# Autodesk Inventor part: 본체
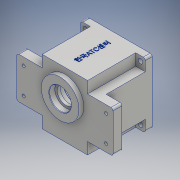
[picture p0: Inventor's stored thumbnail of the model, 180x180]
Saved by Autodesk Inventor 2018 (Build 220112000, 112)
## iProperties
Created: 2020-07
Part Number: 본체
Material: 알루미늄 6061
Document SubType Name: Modeling
Designer: admin
Density: 2.7 g/cm^3
Appearance: 알루미늄 - 평지
Mass: 876.486 g
Surface Area: 793.573 cm^2
Volume: 324.624 cm^3
Author: admin
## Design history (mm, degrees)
sketch "스케치1"
  geometry: L1 (98, 0)-(-98, 0) reference; L2 (0, -65.8)-(0, 65.8) reference; L3 (70, 0)-(70, 30); L4 (70, 30)-(33, 30); L5 (33, 30)-(33, 47); L6 (33, 47)-(-33, 47); L7 (-33, 47)-(-33, 30); L8 (-33, 30)-(-70, 30); L9 (-70, 30)-(-70, 0); L10 (70, 0)-(70, -30); L11 (70, -30)-(33, -30); L12 (33, -30)-(33, -47); L13 (33, -47)-(-33, -47); L14 (-33, -47)-(-33, -30); L15 (-33, -30)-(-70, -30); L16 (-70, -30)-(-70, 0); 1 further point
  constraints: 28 end point, 8 symmetric about line, 5 perpendicular, 2 point on line, 2 vertical
  dimensions: "d0" = 30 distance of L3.start L3.end; "d1" = 47 distance between parallel lines of L1 L6; "d2" = 140 distance between parallel lines of L9 L3; "d3" = 66 distance of L5.end L6.end
extrude "돌출1" new body sketch "스케치1" distance "d4" = 13; taper "d5" = 0 deg
sketch "스케치2"
  geometry: L1 (-98, 0)-(98, 0) reference; L2 (0, -65.8)-(0, 65.8) reference; C1 r 27.5 at (0, 11); 1 further point
  constraints: 1 centre point, 1 point on line
  dimensions: "d6" = 55 diameter of C1; "d7" = 11 distance from line of L1 C1.centre
extrude "돌출2" join sketch "스케치2" distance "d8" = 7; taper "d9" = 0 deg
sketch "스케치3"
  geometry: L1 (-98, 0)-(98, 0) reference; L2 (0, 65.8)-(0, -65.8) reference; L3 (47, -47)-(-47, -47); L4 (-47, -47)-(-47, 47); L5 (-47, 47)-(47, 47); L6 (47, 47)-(47, -47); L7 (47, -47)-(-47, 47); L8 (-47, -47)-(47, 47); 1 further point
  constraints: 12 end point, 2 midpoint, 2 parallel, 1 horizontal, 1 perpendicular
  dimensions: "d10" = 94 distance of L4.end L5.end; "d11" = 94 distance of L3.end L4.end
extrude "돌출3" join sketch "스케치3" distance "d12" = 67; taper "d13" = 0 deg
sketch "스케치5"
  geometry: L1 (33, 30)-(47, 30) reference; L2 (47, 30)-(47, 47) reference; L3 (47, 47)-(33, 47) reference; L4 (33, 47)-(33, 30) reference; L5 (-98, 0)-(98, 0) reference; L6 (0, -65.8)-(0, 65.8) reference; L7 (33, 30)-(47, 30) reference; L8 (33, 47)-(33, 30); L9 (33, 30)-(47, 30); L10 (47, 30)-(47, 47); L11 (47, 30)-(70, 30) reference; L12 (33, 47)-(33, 30) reference; L13 (47, 47)-(33, 47); L14 (-33, 47)-(-33, 30); L15 (-47, 47)-(-33, 47); L16 (-47, 30)-(-47, 47); L17 (-33, 30)-(-47, 30); L18 (47, -30)-(47, -47); L19 (47, -47)-(33, -47); L20 (47, -30)-(47, -47); L21 (47, -47)-(33, -47); L22 (33, -47)-(33, -30); L23 (33, -30)-(47, -30); L24 (33, -47)-(33, -30); L25 (33, -30)-(47, -30); L26 (-33, -30)-(-47, -30); L27 (-33, -47)-(-33, -30); L28 (-47, -47)-(-33, -47); L29 (-47, -30)-(-47, -47); 1 further point
  constraints: 40 end point, 12 symmetric about line, 3 perpendicular, 1 collinear
extrude "돌출4" cut sketch "스케치5" distance "d14" = 70; taper "d15" = 0 deg
sketch "스케치6"
  geometry: L1 (-98, 0)-(98, 0) reference; L2 (0, 65.8)-(0, -65.8) reference; C1 r 43 at (0, 0); 1 further point
  constraints: 1 centre point, 1 coincident
  dimensions: "d16" = 86 diameter of C1
extrude "돌출5" cut sketch "스케치6" distance "d17" = 9; taper "d18" = 0 deg
sketch "스케치7"
  geometry: C1 r 40 at (0, 0); 1 further point
  constraints: 1 centre point, 1 coincident
  dimensions: "d19" = 80 diameter of C1
extrude "돌출6" cut sketch "스케치7" distance "d20" = 62; taper "d21" = 0 deg
sketch "스케치8"
  geometry: L1 (-98, 0)-(98, 0) reference; L2 (0, 65.8)-(0, -65.8) reference; A1 r 21 centre (0, -11) between (-8.978, 7.984) and (8.978, 7.984); A2 r 15 centre (0, 20) between (8.978, 7.984) and (-8.978, 7.984); 1 further point
  constraints: 4 point on circle, 2 centre point, 2 point on line
  dimensions: "d22" = 30 diameter of A2; "d23" = 42 diameter of A1; "d24" = 11 distance from line of L1 A1.centre; "d25" = 20 distance from line of L1 A2.centre
extrude "돌출7" join sketch "스케치8" distance "d26" = 7; taper "d27" = 0 deg
sketch "스케치9"
  geometry: C1 r 40 at (0, 0) reference; C2 r 11 at (0, 20); A1 r 15 centre (0, 20) between (8.978, 7.984) and (-8.978, 7.984) reference; A2 r 21 centre (0, -11) between (-8.978, 7.984) and (8.978, 7.984) reference; 1 further point
  constraints: 1 centre point, 1 coincident
  dimensions: "d28" = 22 diameter of C2
extrude "돌출8" cut sketch "스케치9" distance "d29" = 7; taper "d30" = 0 deg
sketch "스케치10"
  geometry: C1 r 11 at (0, 0) reference; C2 r 9.5 at (0, 0); 1 further point
  constraints: 1 centre point, 1 coincident
  dimensions: "d31" = 19 diameter of C2
extrude "돌출9" cut sketch "스케치10" distance "d32" = 3; taper "d33" = 0 deg
sketch "스케치11"
  geometry: L1 (-24.4, 0)-(97.4, 0) reference; L2 (0, -65.8)-(0, 65.8) reference; L3 (-7, 38.5)-(-7, -16.5) reference; L4 (16, -7.984)-(16, 32) reference; L5 (-27.789, 11)-(37.16, 11); L6 (-7, 27)-(1.3, 27); L7 (1.3, 27)-(1.3, 23.5); L8 (1.3, 23.5)-(6, 23.5); L9 (6, 23.5)-(6, 28.5); L10 (9, 40)-(9, -40) reference; L11 (6, 28.5)-(16, 28.5); L12 (-7, 27)-(-7, 11); L13 (-7, 11)-(16, 11); L14 (16, 11)-(16, 28.5); 1 further point
  constraints: 18 end point, 5 perpendicular, 5 point on line, 1 horizontal, 1 midpoint, 1 parallel
  dimensions: "d34" = 11 distance between parallel lines of L1 L5; "d35" = 32 diameter of L6 L5; "d36" = 25 diameter of L8 L5; "d37" = 35 diameter of L11 L5; "d38" = 8.3 distance of L6.start L6.end; "d39" = 10 distance of L9.end L11.end
revolve "회전1" sketch "스케치11" stored, may be unused: angle "d40" = 90 deg
sketch "스케치12"
  geometry: L1 (-98, 0)-(98, 0) reference; L2 (0, 65.8)-(0, -65.8) reference; L3 (39.799, 4)-(35.777, 4); L4 (39.799, -4)-(35.777, -4); L5 (-39.799, -4)-(-35.777, -4); L6 (-39.799, 4)-(-35.777, 4); A1 r 36 centre (0, 0) between (36, 0) and (35.777, 4); A2 r 4 centre (36, 0) between (36, 4) and (36, -4); A3 r 40 centre (0, 0) between (39.799, -4) and (39.799, 4); A4 r 4 centre (-36, 0) between (-36, -4) and (-36, 4); A5 r 40 centre (0, 0) between (-39.799, 4) and (-39.799, -4); 1 further point
  constraints: 11 point on circle, 8 end point, 7 symmetric about line, 5 centre point, 5 point on line, 2 coincident, 2 horizontal, 2 tangent, 2 other
  dimensions: "d41" = 72 diameter of A1; "d42" = 8 diameter of A2; "d44" = 40 radius of A3
extrude "돌출10" join sketch "스케치12" stored distance "d45" = 0; taper "d46" = 0 deg
sketch "스케치13"
  geometry: L1 (-98, 0)-(98, 0) reference; L2 (0, 65.8)-(0, -65.8) reference; 5 further points
  constraints: 3 symmetric about line
  dimensions: "d47" = 19 distance from line of L1 point (60, 19); "d48" = 60 distance from line of L2 point (60, 19)
hole "구멍1" sketch "스케치13" at (60, 19), (-60, 19), (-60, -19), (60, -19) diameter "d49" = 4.5; stored, may be unused: countersink angle "d53" = 90 deg, drill point angle "d55" = 118 deg; dims "d50" = 6, "d51" = 10, "d52" = 5, "d54" = 8
sketch "스케치14"
  geometry: L1 (47, 30)-(33, 30) reference; L2 (47, 47)-(47, 30) reference; L3 (33, 47)-(47, 47) reference; L4 (33, 30)-(33, 47) reference; L5 (-98, 0)-(98, 0) reference; L6 (0, -65.8)-(0, 65.8) reference; C1 r 3.5 at (40, 40); C2 r 3.5 at (-40, 40); C3 r 3.5 at (40, -40); C4 r 3.5 at (-40, -40); 1 further point
  constraints: 4 centre point, 3 symmetric about line, 3 other
  dimensions: "d56" = 40 distance from line of L6 C1.centre; "d57" = 40 distance from line of L5 C1.centre; "d58" = 7 diameter of C1
extrude "돌출11" cut sketch "스케치14" stored distance "d59" = 0; taper "d60" = 0 deg
sketch "스케치15"
  geometry: L1 (39.799, -4)-(36, -4) reference; L2 (36, 4)-(39.799, 4) reference; L3 (-39.799, 4)-(-36, 4) reference; L4 (-36, -4)-(-39.799, -4) reference; A1 r 4 centre (36, 0) between (36, 4) and (36, -4) reference; A2 r 40 centre (0, 0) between (39.799, 4) and (-39.799, 4) reference; A3 r 4 centre (-36, 0) between (-36, -4) and (-36, 4) reference; A4 r 40 centre (0, 0) between (-39.799, -4) and (39.799, -4) reference; A5 r 15 centre (0, 20) between (8.978, 7.984) and (-8.978, 7.984) reference; A6 r 21 centre (0, -11) between (-8.978, 7.984) and (8.978, 7.984) reference; 3 further points
  constraints: 2 coincident
hole "구멍2" sketch "스케치15" at (-36, 0), (36, 0) diameter "d61" = 3.242; stored, may be unused: countersink angle "d65" = 90 deg, drill point angle "d67" = 118 deg; dims "d62" = 7, "d63" = 10, "d64" = 5, "d66" = 9
chamfer "모따기1" distance "d68" = 1; stored, may be unused: second distance "d69" = 2, angle "d70" = 45 deg
chamfer "모따기2" distance "d71" = 0.8; stored, may be unused: second distance "d72" = 2, angle "d73" = 30 deg
fillet "모깎기1" dims "d74" = 3
sketch "스케치16"
  geometry: L1 (77, 80)-(-11, 80) reference; L2 (33, -24.4)-(33, 97.4) reference; 2 further points
  constraints: 1 point on line, 1 other
  dimensions: "d75" = 40 distance from line of L1 point (33, 40)
feature "엠보싱1" sketch "스케치16" dims "d0" = 30, "d1" = 47, "d2" = 140, "d3" = 66, "d76" = 0.5, "d77" = 0
node "솔리드1"
node "투영된 루프1"
node "투영된 루프2"
node "투영된 루프3"
node "투영된 루프4"
node "투영된 루프5"
